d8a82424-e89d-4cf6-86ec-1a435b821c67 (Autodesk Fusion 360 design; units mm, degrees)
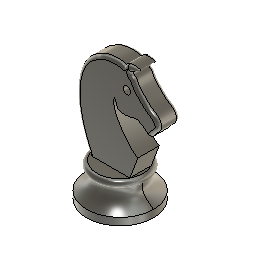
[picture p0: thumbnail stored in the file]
sketch "Sketch1" plane through (0, 0, 0) normal (0, 1, 0) x axis (1, 0, 0)
  line L1 (10, 0) -> (0, 0)
  line L2 (0, -55) -> (0, 0)
  line L3 (0, -10) -> (0, 0)
  line L4 (6.9022, -10) -> (0, -10)
  line L5 (10, -2.1936) -> (10, 0)
  curve K1 (10, -2.1936) -> (6.9022, -7.8644)
  arc A1 centre (6.9022, -8.9322) radius 1.0678 clockwise from (6.9022, -7.8644) to (6.9022, -10)
  point P1 (0, 0)
  point P2 (0, 0)
  point P4 (0, 0)
  point P3 (10, 0)
  point P5 (0, -55)
  point P6 (0, -10)
  coincident P1 P2
  horizontal L1
  coincident P1 P4
  perpendicular L1 L2
  perpendicular L1 L3
  perpendicular L2 L4
  tangent L4 A1
  perpendicular L1 L5
  dimension "d1" distance P2 P3 = 10
  dimension "d2" distance P4 P5 = 55
  dimension "d3" distance P2 P6 = 10
revolve "Revolve1" sketch "Sketch1" AlongAngle 360
canvas "Canvas1"
sketch "Sketch2" plane through (0, 0, 0) normal (0, 1, 0) x axis (1, 0, 0)
  line L1 (8.5639, -16.4291) -> (6.1066, -9.9893)
  curve K1 (1.4659, -28.5572) -> (8.5639, -16.4291)
  curve K2 (12.369, -23.5599) -> (1.4659, -28.5572)
  curve K3 (-5.97, -9.8745) -> (12.369, -23.5599)
  line L2 (6.1066, -9.9893) -> (-5.97, -9.8745)
  circle C1 centre (5.235, -32.3425) radius 1.1242
extrude "Extrude1" add sketch "Sketch2" distance 3.205
fillet "Fillet1" radius 1
fillet "Fillet2" radius 1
